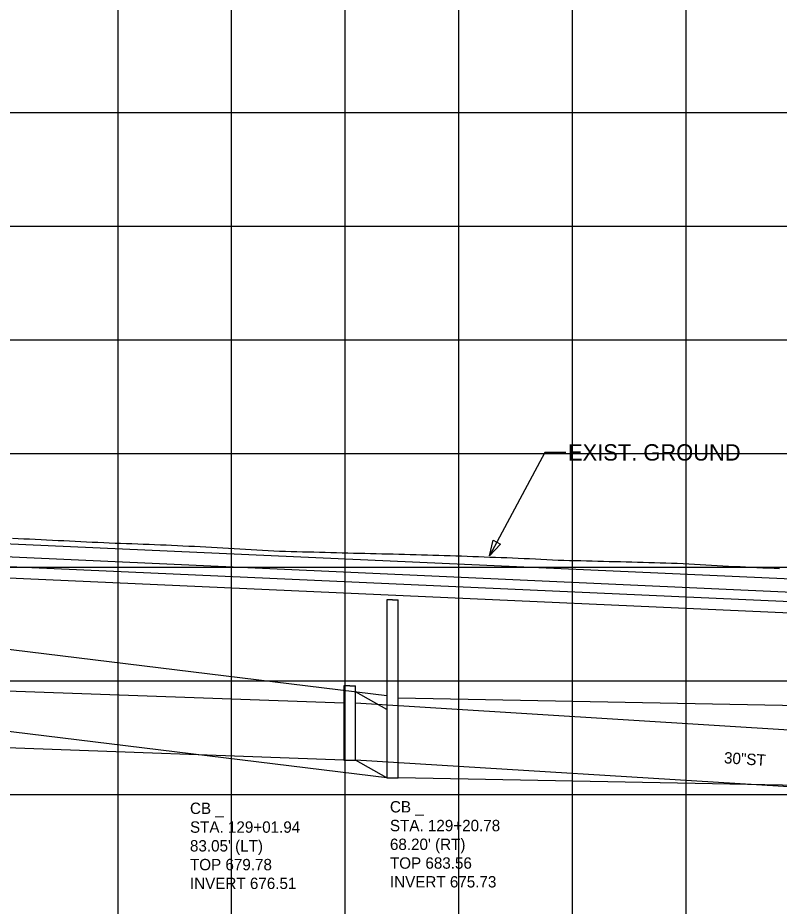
# Model space of a CAD drawing. Extents: x -7164 to 2214450, y -19642 to 253469.
# Drawn here: x 6755.9 to 7091, y -2799.2 to -2408.4 of the extents above; entities that cross this region are included whole.
import ezdxf

# ---------------------------------------------------------------- set-up
doc = ezdxf.new("R2010")
doc.units = 0
for name, color, linetype in [('DESIGN - PROFILE - Proposed', 7, 'Continuous'), ('DESIGN - PROFILE - Proposed Text', 7, 'Continuous'), ('DESIGN - SHEET - Light Grid', 7, 'Continuous'), ('SURVEY - PROFILE - Drainage - Storm Sewer', 7, 'Continuous'), ('SURVEY - PROFILE - Drainage - Storm Sewer Text', 7, 'Continuous'), ('SURVEY - PROFILE - Ground Line with Text', 7, 'Continuous'), ('SURVEY - PROFILE - Utilities - Cable with Text', 7, 'Continuous'), ('SURVEY - PROFILE - Utilities - Electric with Text', 7, 'Continuous'), ('XTREE', 7, 'Continuous')]:
    doc.layers.add(name, color=color, linetype=linetype)

msp = doc.modelspace()

# ---------------------------------------------------------------- linework, layer by layer
at = {"layer": 'DESIGN - PROFILE - Proposed'}
msp.add_line((6700, -2643.11), (7725, -2689.23), dxfattribs=at)
msp.add_line((6700, -2643.11), (7725, -2689.23), dxfattribs=at)
at = {"layer": 'DESIGN - PROFILE - Proposed Text'}
msp.add_lwpolyline([(6997, -2599.54), (6987.82, -2599.54), (6963.45, -2645)], dxfattribs=at)
msp.add_lwpolyline([(6997, -2599.54), (6987.82, -2599.54), (6963.45, -2645)], dxfattribs=at)
msp.add_lwpolyline([(6968.24, -2639.9), (6963.45, -2645), (6965.04, -2638.18)], close=True, dxfattribs=at)
msp.add_lwpolyline([(6968.24, -2639.9), (6963.45, -2645), (6965.04, -2638.18)], close=True, dxfattribs=at)
at = {"layer": 'DESIGN - SHEET - Light Grid'}
for p, q in [((6800, -3000), (6800, -1000)), ((6800, -3000), (6800, -1000)), ((6850, -3000), (6850, -1000)), ((6850, -3000), (6850, -1000)), ((6900, -3000), (6900, -1000)), ((6900, -3000), (6900, -1000)), ((6950, -3000), (6950, -1000)), ((6950, -3000), (6950, -1000)), ((7000, -3000), (7000, -1000)), ((7000, -3000), (7000, -1000)), ((7050, -3000), (7050, -1000)), ((7050, -3000), (7050, -1000)), ((0, -2450), (12400, -2450)), ((0, -2450), (12400, -2450)), ((0, -2500), (12400, -2500)), ((0, -2500), (12400, -2500)), ((0, -2550), (12400, -2550)), ((0, -2550), (12400, -2550)), ((0, -2600), (12400, -2600)), ((0, -2600), (12400, -2600)), ((0, -2650), (12400, -2650)), ((0, -2650), (12400, -2650)), ((0, -2700), (12400, -2700)), ((0, -2700), (12400, -2700)), ((0, -2750), (12400, -2750)), ((0, -2750), (12400, -2750))]:
    msp.add_line(p, q, dxfattribs=at)
at = {"layer": 'SURVEY - PROFILE - Drainage - Storm Sewer'}
for p, q in [((6918.28, -2706.67), (5603.14, -2545.4)), ((6918.28, -2706.67), (5603.14, -2545.4)), ((6918.28, -2742.67), (5603.14, -2581.4)), ((6918.28, -2742.67), (5603.14, -2581.4)), ((6920.78, -2664.36), (6918.28, -2664.36)), ((6918.28, -2664.36), (6918.28, -2742.67)), ((6920.78, -2664.36), (6918.28, -2664.36)), ((6918.28, -2664.36), (6918.28, -2742.67)), ((6920.78, -2664.36), (6923.28, -2664.36)), ((6920.78, -2664.36), (6923.28, -2664.36)), ((6923.28, -2742.67), (6923.28, -2664.36)), ((6923.28, -2742.67), (6923.28, -2664.36)), ((6899.44, -2709.9), (6498.25, -2695.4)), ((6899.44, -2709.9), (6498.25, -2695.4)), ((6901.94, -2702.16), (6899.44, -2702.16)), ((6899.44, -2702.16), (6899.44, -2734.9)), ((6901.94, -2702.16), (6899.44, -2702.16)), ((6899.44, -2702.16), (6899.44, -2734.9)), ((6901.94, -2702.16), (6899.44, -2702.16)), ((6899.44, -2702.16), (6899.44, -2734.9)), ((6901.94, -2702.16), (6899.44, -2702.16)), ((6899.44, -2702.16), (6899.44, -2734.9)), ((6901.94, -2702.16), (6904.44, -2702.16)), ((6901.94, -2702.16), (6904.44, -2702.16)), ((6901.94, -2702.16), (6904.44, -2702.16)), ((6901.94, -2702.16), (6904.44, -2702.16)), ((6904.44, -2734.9), (6904.44, -2702.16)), ((6904.44, -2734.9), (6904.44, -2702.16)), ((6904.44, -2734.9), (6904.44, -2702.16)), ((6904.44, -2734.9), (6904.44, -2702.16)), ((6918.28, -2712.67), (6904.44, -2704.9)), ((6918.28, -2712.67), (6904.44, -2704.9)), ((7297.66, -2714.9), (6923.28, -2707.67)), ((7297.66, -2714.9), (6923.28, -2707.67)), ((7249.49, -2731.2), (6904.44, -2709.9)), ((7249.49, -2731.2), (6904.44, -2709.9)), ((6899.44, -2734.9), (6498.25, -2720.4)), ((6899.44, -2734.9), (6498.25, -2720.4)), ((6899.44, -2734.9), (6904.44, -2734.9)), ((6899.44, -2734.9), (6904.44, -2734.9)), ((6899.44, -2734.9), (6904.44, -2734.9)), ((6899.44, -2734.9), (6904.44, -2734.9)), ((6918.28, -2742.67), (6904.44, -2734.9)), ((7249.49, -2756.2), (6904.44, -2734.9)), ((6918.28, -2742.67), (6904.44, -2734.9)), ((7249.49, -2756.2), (6904.44, -2734.9)), ((6918.28, -2742.67), (6923.28, -2742.67)), ((6918.28, -2742.67), (6923.28, -2742.67)), ((7297.66, -2749.9), (6923.28, -2742.67)), ((7297.66, -2749.9), (6923.28, -2742.67))]:
    msp.add_line(p, q, dxfattribs=at)
at = {"layer": 'SURVEY - PROFILE - Ground Line with Text'}
for points in [[(6753.57, -2637.29), (6756.12, -2637.39), (6758.58, -2637.52), (6761.12, -2637.63), (6763.58, -2637.76), (6766.12, -2637.87), (6768.59, -2638), (6771.12, -2638.11), (6773.65, -2638.24), (6776.12, -2638.35), (6778.67, -2638.48), (6781.12, -2638.59), (6783.68, -2638.72), (6786.12, -2638.83), (6788.69, -2638.96), (6791.12, -2639.07)], [(6753.57, -2637.29), (6756.12, -2637.39), (6758.58, -2637.52), (6761.12, -2637.63), (6763.58, -2637.76), (6766.12, -2637.87), (6768.59, -2638), (6771.12, -2638.11), (6773.65, -2638.24), (6776.12, -2638.35), (6778.67, -2638.48), (6781.12, -2638.59), (6783.68, -2638.72), (6786.12, -2638.83), (6788.69, -2638.96), (6791.12, -2639.07)], [(6791.12, -2639.07), (6793.7, -2639.2), (6796.12, -2639.31), (6798.71, -2639.41), (6801.13, -2639.5), (6803.71, -2639.59), (6806.13, -2639.68), (6808.7, -2639.77), (6811.13, -2639.86), (6813.69, -2639.95), (6816.13, -2640.04), (6818.69, -2640.14), (6821.13, -2640.22), (6823.59, -2640.34), (6826.13, -2640.48), (6828.59, -2640.6), (6831.13, -2640.73), (6833.6, -2640.86), (6836.13, -2640.99), (6838.61, -2641.11), (6841.13, -2641.25), (6843.61, -2641.37), (6846.13, -2641.5), (6848.62, -2641.65), (6851.13, -2641.79), (6853.62, -2641.94), (6856.13, -2642.07), (6858.63, -2642.22), (6861.13, -2642.36), (6863.63, -2642.51), (6866.13, -2642.64), (6868.64, -2642.79), (6871.13, -2642.93), (6873.64, -2643.01), (6876.13, -2643.07), (6878.64, -2643.15), (6881.13, -2643.21), (6883.64, -2643.29), (6886.13, -2643.35), (6888.65, -2643.43), (6891.13, -2643.49), (6893.65, -2643.57), (6896.13, -2643.63), (6898.62, -2643.7), (6901.13, -2643.75), (6903.63, -2643.82), (6906.13, -2643.87), (6908.65, -2643.94), (6911.13, -2643.99), (6913.67, -2644.06), (6916.13, -2644.11), (6918.69, -2644.19), (6921.13, -2644.23), (6923.56, -2644.3), (6926.13, -2644.37), (6928.57, -2644.45), (6931.13, -2644.52), (6933.58, -2644.59), (6936.13, -2644.66), (6938.58, -2644.73), (6941.13, -2644.8), (6943.59, -2644.87), (6946.12, -2644.94), (6948.61, -2645.05), (6951.12, -2645.11), (6953.62, -2645.22), (6956.12, -2645.28), (6958.63, -2645.39), (6961.12, -2645.45), (6963.65, -2645.56), (6966.12, -2645.62), (6968.66, -2645.73), (6971.12, -2645.79), (6973.65, -2645.95), (6976.12, -2646.03), (6978.65, -2646.19), (6981.12, -2646.27), (6983.65, -2646.43), (6986.12, -2646.52), (6988.65, -2646.68), (6991.12, -2646.76), (6993.65, -2646.92), (6996.12, -2647), (6998.66, -2647.04), (7001.12, -2647.12), (7003.67, -2647.16), (7006.12, -2647.24), (7008.67, -2647.28), (7011.12, -2647.35), (7013.68, -2647.39), (7016.12, -2647.47), (7018.69, -2647.51), (7021.12, -2647.59), (7023.56, -2647.68), (7026.12, -2647.72), (7028.57, -2647.81), (7031.12, -2647.85), (7033.58, -2647.95), (7036.12, -2647.99), (7038.59, -2648.08), (7041.12, -2648.12)], [(6791.12, -2639.07), (6793.7, -2639.2), (6796.12, -2639.31), (6798.71, -2639.41), (6801.13, -2639.5), (6803.71, -2639.59), (6806.13, -2639.68), (6808.7, -2639.77), (6811.13, -2639.86), (6813.69, -2639.95), (6816.13, -2640.04), (6818.69, -2640.14), (6821.13, -2640.22), (6823.59, -2640.34), (6826.13, -2640.48), (6828.59, -2640.6), (6831.13, -2640.73), (6833.6, -2640.86), (6836.13, -2640.99), (6838.61, -2641.11), (6841.13, -2641.25), (6843.61, -2641.37), (6846.13, -2641.5), (6848.62, -2641.65), (6851.13, -2641.79), (6853.62, -2641.94), (6856.13, -2642.07), (6858.63, -2642.22), (6861.13, -2642.36), (6863.63, -2642.51), (6866.13, -2642.64), (6868.64, -2642.79), (6871.13, -2642.93), (6873.64, -2643.01), (6876.13, -2643.07), (6878.64, -2643.15), (6881.13, -2643.21), (6883.64, -2643.29), (6886.13, -2643.35), (6888.65, -2643.43), (6891.13, -2643.49), (6893.65, -2643.57), (6896.13, -2643.63), (6898.62, -2643.7), (6901.13, -2643.75), (6903.63, -2643.82), (6906.13, -2643.87), (6908.65, -2643.94), (6911.13, -2643.99), (6913.67, -2644.06), (6916.13, -2644.11), (6918.69, -2644.19), (6921.13, -2644.23), (6923.56, -2644.3), (6926.13, -2644.37), (6928.57, -2644.45), (6931.13, -2644.52), (6933.58, -2644.59), (6936.13, -2644.66), (6938.58, -2644.73), (6941.13, -2644.8), (6943.59, -2644.87), (6946.12, -2644.94), (6948.61, -2645.05), (6951.12, -2645.11), (6953.62, -2645.22), (6956.12, -2645.28), (6958.63, -2645.39), (6961.12, -2645.45), (6963.65, -2645.56), (6966.12, -2645.62), (6968.66, -2645.73), (6971.12, -2645.79), (6973.65, -2645.95), (6976.12, -2646.03), (6978.65, -2646.19), (6981.12, -2646.27), (6983.65, -2646.43), (6986.12, -2646.52), (6988.65, -2646.68), (6991.12, -2646.76), (6993.65, -2646.92), (6996.12, -2647), (6998.66, -2647.04), (7001.12, -2647.12), (7003.67, -2647.16), (7006.12, -2647.24), (7008.67, -2647.28), (7011.12, -2647.35), (7013.68, -2647.39), (7016.12, -2647.47), (7018.69, -2647.51), (7021.12, -2647.59), (7023.56, -2647.68), (7026.12, -2647.72), (7028.57, -2647.81), (7031.12, -2647.85), (7033.58, -2647.95), (7036.12, -2647.99), (7038.59, -2648.08), (7041.12, -2648.12)], [(7041.12, -2648.12), (7043.6, -2648.21), (7046.12, -2648.25), (7048.64, -2648.43), (7051.12, -2648.54), (7053.65, -2648.72), (7056.12, -2648.82), (7058.66, -2649), (7061.12, -2649.11), (7063.67, -2649.29), (7066.12, -2649.4), (7068.68, -2649.57), (7071.12, -2649.68), (7073.71, -2649.8), (7076.12, -2649.91), (7078.72, -2650.03), (7081.12, -2650.15), (7083.74, -2650.27), (7086.12, -2650.38), (7088.75, -2650.5), (7091.12, -2650.61)], [(7041.12, -2648.12), (7043.6, -2648.21), (7046.12, -2648.25), (7048.64, -2648.43), (7051.12, -2648.54), (7053.65, -2648.72), (7056.12, -2648.82), (7058.66, -2649), (7061.12, -2649.11), (7063.67, -2649.29), (7066.12, -2649.4), (7068.68, -2649.57), (7071.12, -2649.68), (7073.71, -2649.8), (7076.12, -2649.91), (7078.72, -2650.03), (7081.12, -2650.15), (7083.74, -2650.27), (7086.12, -2650.38), (7088.75, -2650.5), (7091.12, -2650.61)]]:
    msp.add_lwpolyline(points, dxfattribs=at)
at = {"layer": 'SURVEY - PROFILE - Utilities - Cable with Text'}
msp.add_lwpolyline([(3997.12, -2279.89), (4802.54, -2306.2), (4934.37, -2314.54), (5070.11, -2333.66), (5216, -2365.19), (5366.92, -2411.25), (5566.4, -2489.8), (5665.47, -2523.85), (5822.06, -2559.45), (6138.57, -2601.37), (6627.33, -2649.15), (7125.24, -2671.48), (7800.39, -2701.43), (8331.65, -2716.63), (8778.24, -2733.74), (9263.15, -2746.41), (9418.17, -2746.77)], dxfattribs=at)
msp.add_lwpolyline([(3997.12, -2279.89), (4802.54, -2306.2), (4934.37, -2314.54), (5070.11, -2333.66), (5216, -2365.19), (5366.92, -2411.25), (5566.4, -2489.8), (5665.47, -2523.85), (5822.06, -2559.45), (6138.57, -2601.37), (6627.33, -2649.15), (7125.24, -2671.48), (7800.39, -2701.43), (8331.65, -2716.63), (8778.24, -2733.74), (9263.15, -2746.41), (9418.17, -2746.77)], dxfattribs=at)
at = {"layer": 'SURVEY - PROFILE - Utilities - Electric with Text'}
for points in [[(3998.08, -2269.94), (4803.35, -2291.22), (4935.9, -2299.6), (5072.75, -2318.88), (5219.78, -2350.66), (5371.86, -2397.08), (5571.59, -2475.72), (5669.58, -2509.4), (5824.72, -2544.67), (6140.29, -2586.46), (6628.39, -2634.18), (7125.91, -2656.49), (7800.94, -2686.44), (8332.15, -2701.64), (8778.73, -2718.74), (9263.36, -2731.41), (9327.02, -2731.56)], [(3998.08, -2269.94), (4803.35, -2291.22), (4935.9, -2299.6), (5072.75, -2318.88), (5219.78, -2350.66), (5371.86, -2397.08), (5571.59, -2475.72), (5669.58, -2509.4), (5824.72, -2544.67), (6140.29, -2586.46), (6628.39, -2634.18), (7125.91, -2656.49), (7800.94, -2686.44), (8332.15, -2701.64), (8778.73, -2718.74), (9263.36, -2731.41), (9327.02, -2731.56)], [(3997.6, -2274.92), (4802.81, -2301.21), (4934.88, -2309.56), (5070.99, -2328.73), (5217.26, -2360.35), (5368.56, -2406.53), (5568.13, -2485.11), (5666.84, -2519.04), (5822.95, -2554.52), (6139.14, -2596.4), (6627.68, -2644.16), (7125.46, -2666.48), (7800.57, -2696.44), (8331.81, -2711.63), (8778.4, -2728.74), (9263.22, -2741.41), (9422.06, -2741.78), (9638.89, -2735.54), (10010.38, -2723.15), (10421.06, -2712.22), (10492.02, -2711.61), (10506.89, -2711.72), (10626.17, -2716.95), (10629.65, -2717.02)], [(3997.6, -2274.92), (4802.81, -2301.21), (4934.88, -2309.56), (5070.99, -2328.73), (5217.26, -2360.35), (5368.56, -2406.53), (5568.13, -2485.11), (5666.84, -2519.04), (5822.95, -2554.52), (6139.14, -2596.4), (6627.68, -2644.16), (7125.46, -2666.48), (7800.57, -2696.44), (8331.81, -2711.63), (8778.4, -2728.74), (9263.22, -2741.41), (9422.06, -2741.78), (9638.89, -2735.54), (10010.38, -2723.15), (10421.06, -2712.22), (10492.02, -2711.61), (10506.89, -2711.72), (10626.17, -2716.95), (10629.65, -2717.02)]]:
    msp.add_lwpolyline(points, dxfattribs=at)
at = {"layer": 'XTREE'}
msp.add_line((6450, -2631.86), (7775, -2691.48), dxfattribs=at)
msp.add_line((6450, -2631.86), (7775, -2691.48), dxfattribs=at)

# ---------------------------------------------------------------- texts
at = {"layer": 'DESIGN - PROFILE - Proposed Text'}
msp.add_text('EXIST. GROUND', height=7.2, dxfattribs=at).set_placement((6998, -2603.14))
msp.add_text('EXIST. GROUND', height=7.2, dxfattribs=at).set_placement((6998, -2603.14))
at = {"layer": 'SURVEY - PROFILE - Drainage - Storm Sewer Text'}
msp.add_text('30"ST', height=5, rotation=356.2449, dxfattribs=at).set_placement((7066.53, -2736.28))
msp.add_text('30"ST', height=5, rotation=356.2449, dxfattribs=at).set_placement((7066.53, -2736.28))
for s, p in [('CB _', (6831.67, -2758.6)), ('CB _', (6831.67, -2758.6)), ('CB _', (6919.66, -2757.93)), ('CB _', (6919.66, -2757.93)), ('STA. 129+01.94', (6831.67, -2766.85)), ('STA. 129+01.94', (6831.67, -2766.85)), ('STA. 129+20.78', (6919.66, -2766.18)), ('STA. 129+20.78', (6919.66, -2766.18)), ("83.05' (LT)", (6831.67, -2775.1)), ("83.05' (LT)", (6831.67, -2775.1)), ("68.20' (RT)", (6919.66, -2774.43)), ("68.20' (RT)", (6919.66, -2774.43)), ('TOP 679.78', (6831.67, -2783.35)), ('TOP 679.78', (6831.67, -2783.35)), ('TOP 683.56', (6919.66, -2782.68)), ('TOP 683.56', (6919.66, -2782.68)), ('INVERT 676.51', (6831.67, -2791.6)), ('INVERT 676.51', (6831.67, -2791.6)), ('INVERT 675.73', (6919.66, -2790.93)), ('INVERT 675.73', (6919.66, -2790.93))]:
    msp.add_text(s, height=5, dxfattribs=at).set_placement(p)

doc.saveas('drawing.dxf')
